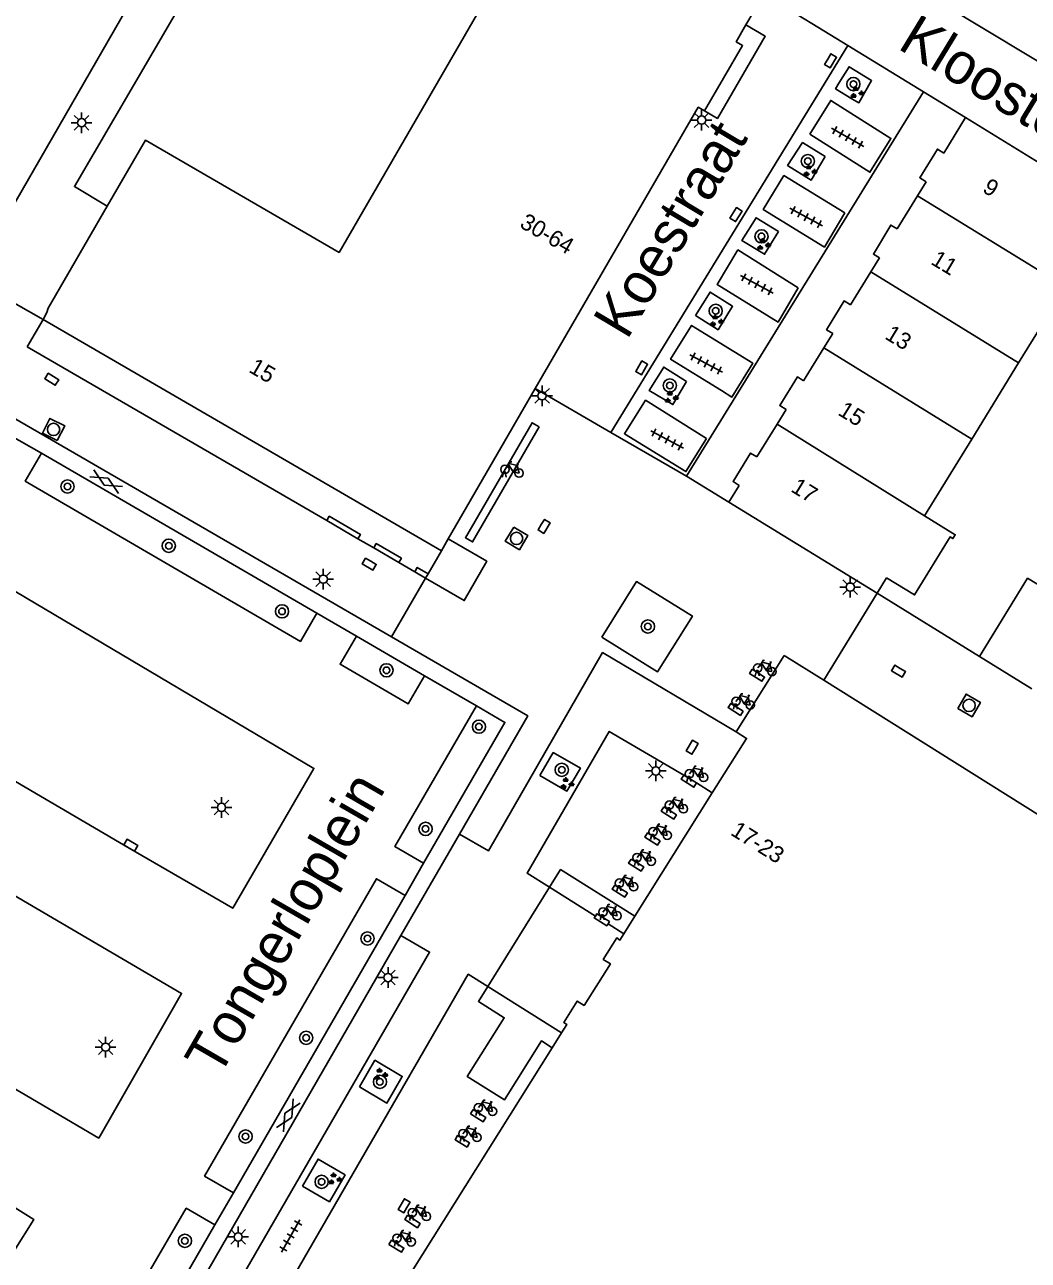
# Model space of a CAD drawing. Extents: x 136000 to 141014, y 402000 to 403500.
# Drawn here: x 138025.6 to 138086.4, y 402294.1 to 402368.9 of the extents above; entities that cross this region are included whole.
import ezdxf

# ---------------------------------------------------------------- set-up
doc = ezdxf.new("R2010")
doc.units = 0
for name, color, linetype in [('gg-afsc-hekwerk', 7, 'Continuous'), ('gg-afsc-muur', 7, 'Continuous'), ('gg-anno-huisnummerreeks BGT', 7, 'Continuous'), ('gg-anno-openbare ruimte label', 7, 'Continuous'), ('gg-bbg-bijgebouw', 7, 'Continuous'), ('gg-bbg-gedigitaliseerde bijgebouw', 7, 'Continuous'), ('gg-bbg-hoofdgebouw', 7, 'Continuous'), ('gg-bbg-luifel en loopbrug', 7, 'Continuous'), ('gg-bbg-onder overbouw', 7, 'Continuous'), ('gg-bbg-pand overbouw', 7, 'Continuous'), ('gg-bbg-pilaar onder overbouw', 7, 'Continuous'), ('gg-bbg-pilaar pand', 7, 'Continuous'), ('gg-bbg-tussenscheiding', 7, 'Continuous'), ('gg-knt-verharding', 7, 'Continuous'), ('gg-knt-verharding nz', 7, 'Continuous'), ('gt-grn-weggrens', 7, 'Continuous'), ('gt-symb-boom', 7, 'Continuous'), ('gt-symb-fietsenrek', 7, 'Continuous'), ('gt-symb-gesloten verharding', 7, 'Continuous'), ('gt-symb-groenvak', 7, 'Continuous'), ('gt-symb-kolk', 7, 'Continuous'), ('gt-symb-lichtmast', 7, 'Continuous'), ('gt-symb-rioolschacht', 7, 'Continuous'), ('gt-symb-tegel verharding', 7, 'Continuous')]:
    doc.layers.add(name, color=color, linetype=linetype)

# ---------------------------------------------------------------- blocks, each defined once
blk = doc.blocks.new('gt0-GRVAK')
at = {"layer": 'gt-symb-groenvak'}
for p, q in [((-0.11, 0.189), (-0.228, 0.24)), ((-0.182, 0.153), (0.088, 0.153)), ((-0.091, 0.211), (-0.156, 0.322)), ((-0.047, 0.214), (-0.047, 0.393)), ((-0.004, 0.211), (0.061, 0.322)), ((0.015, 0.189), (0.133, 0.24)), ((0.262, -0.052), (0.197, 0.059)), ((0.305, -0.049), (0.305, 0.13)), ((0.349, -0.052), (0.414, 0.059)), ((-0.245, -0.228), (-0.363, -0.177)), ((-0.318, -0.264), (-0.047, -0.264)), ((-0.226, -0.206), (-0.291, -0.095)), ((-0.183, -0.203), (-0.183, -0.024)), ((-0.139, -0.206), (-0.074, -0.095)), ((-0.12, -0.228), (-0.002, -0.177)), ((0.243, -0.074), (0.125, -0.023)), ((0.17, -0.11), (0.441, -0.11)), ((0.368, -0.074), (0.486, -0.023))]:
    blk.add_line(p, q, dxfattribs=at)
blk = doc.blocks.new('gt0-TEG1')
at = {"layer": 'gt-symb-tegel verharding'}
for p, q in [((-1.125, 0), (1.125, 0)), ((-0.9, -0.25), (-0.9, 0.25)), ((-0.45, -0.25), (-0.45, 0.25)), ((0, -0.25), (0, 0.25)), ((0.45, -0.25), (0.45, 0.25)), ((0.9, -0.25), (0.9, 0.25))]:
    blk.add_line(p, q, dxfattribs=at)
blk = doc.blocks.new('gt0-BOOM')
at = {"layer": 'gt-symb-boom'}
for radius in [0.4, 0.2]:
    blk.add_circle((0, 0), radius, dxfattribs=at)
blk = doc.blocks.new('gt0-KOLK')
at = {"layer": 'gt-symb-kolk'}
blk.add_lwpolyline([(0, 0), (0.375, 0), (0.375, 0.4), (-0.375, 0.4), (-0.375, 0), (0, 0)], dxfattribs=at)
blk = doc.blocks.new('gt0-LMAST')
at = {"layer": 'gt-symb-lichtmast'}
for p, q in [((-0.182, 0.173), (-0.447, 0.438)), ((-0.005, 0.246), (-0.005, 0.621)), ((0.172, 0.173), (0.437, 0.438)), ((-0.255, -0.004), (-0.63, -0.004)), ((-0.182, -0.181), (-0.447, -0.446)), ((-0.005, -0.254), (-0.005, -0.629)), ((0.437, -0.446), (0.172, -0.181)), ((0.245, -0.004), (0.62, -0.004))]:
    blk.add_line(p, q, dxfattribs=at)
blk.add_circle((-0.005, -0.004), 0.25, dxfattribs=at)
blk = doc.blocks.new('gt0-RS')
at = {"layer": 'gt-symb-rioolschacht'}
blk.add_lwpolyline([(-0.5, -0.5), (0.5, -0.5), (0.5, 0.5), (-0.5, 0.5)], close=True, dxfattribs=at)
blk.add_circle((0, 0), 0.375, dxfattribs=at)
blk = doc.blocks.new('gt0-FREK')
at = {"layer": 'gt-symb-fietsenrek'}
for p, q in [((0.259, 0.762), (0.294, 0.823)), ((0.54, 0.335), (0.259, 0.762)), ((0.294, 0.823), (0.767, 0.714)), ((0.757, 0.841), (0.866, 0.816)), ((0.767, 0.714), (0.84, 0.822)), ((0.767, 0.714), (0.54, 0.335)), ((0.895, 0.252), (0.767, 0.714))]:
    blk.add_line(p, q, dxfattribs=at)
for points in [[(0.036, 0.476), (0.228, 0.708), (0.259, 0.762)], [(0.294, 0.823), (0.36, 0.937), (0.452, 0.935)], [(-0.124, 0), (-0.047, 0.312), (0.053, 0.312), (0.12, 0)], [(0.54, 0.335), (0.555, 0.305), (0.895, 0.252)]]:
    blk.add_lwpolyline(points, dxfattribs=at)
for centre in [(0.036, 0.476), (0.895, 0.252)]:
    blk.add_circle(centre, 0.252, dxfattribs=at)
blk = doc.blocks.new('gt0-GESVH1')
at = {"layer": 'gt-symb-gesloten verharding'}
for p, q in [((-0.992, -0.261), (0.008, 0.239)), ((0.008, -0.261), (-0.992, 0.239)), ((0.008, 0.239), (1.008, -0.261)), ((1.008, 0.239), (0.008, -0.261))]:
    blk.add_line(p, q, dxfattribs=at)

msp = doc.modelspace()

# ---------------------------------------------------------------- linework, layer by layer
at = {"layer": 'gg-afsc-hekwerk'}
msp.add_lwpolyline([(138030.63, 402357.914), (138028.649, 402359.103), (138041.892, 402381.79)], dxfattribs=at)
at = {"layer": 'gg-afsc-muur'}
msp.add_line((138083.443, 402330.652), (138077.24, 402334.501), dxfattribs=at)
at = {"layer": 'gg-bbg-bijgebouw'}
msp.add_line((138086.593, 402328.703), (138083.443, 402330.652), dxfattribs=at)
at = {"layer": 'gg-bbg-gedigitaliseerde bijgebouw'}
msp.add_lwpolyline([(138087.459, 402334.706), (138086.344, 402335.391), (138083.443, 402330.652)], dxfattribs=at)
at = {"layer": 'gg-bbg-hoofdgebouw'}
for p, q in [((138033.741, 402373.25), (138022.397, 402353.534)), ((138069.3, 402368.888), (138070.387, 402370.763)), ((138081.273, 402361.135), (138082.596, 402363.284)), ((138082.596, 402363.284), (138091.544, 402357.769)), ((138079.684, 402358.553), (138080.207, 402359.402)), ((138078.445, 402356.541), (138079.684, 402358.553)), ((138027.063, 402351.754), (138030.63, 402357.914)), ((138076.849, 402353.947), (138077.374, 402354.801)), ((138075.621, 402351.952), (138076.849, 402353.947)), ((138088.636, 402353.038), (138085.803, 402348.43)), ((138074.013, 402349.338), (138074.549, 402350.209)), ((138072.788, 402347.348), (138074.013, 402349.338)), ((138085.803, 402348.43), (138082.969, 402343.82)), ((138051.276, 402337.772), (138056.547, 402346.876)), ((138071.178, 402344.731), (138071.723, 402345.616)), ((138069.954, 402342.742), (138071.178, 402344.731)), ((138082.969, 402343.82), (138080.11, 402339.17)), ((138068.264, 402339.997), (138068.89, 402341.014)), ((138077.24, 402334.501), (138068.264, 402339.997)), ((138050.86, 402337.054), (138051.276, 402337.772)), ((138077.807, 402335.423), (138077.24, 402334.501)), ((138068.709, 402326.089), (138071.619, 402330.716)), ((138074.005, 402329.218), (138071.619, 402330.716)), ((138107.245, 402308.347), (138074.005, 402329.218)), ((138067.262, 402322.4), (138062.573, 402314.932)), ((138062.573, 402314.932), (138061.905, 402313.868)), ((138058.143, 402307.877), (138057.574, 402306.97)), ((138057.574, 402306.97), (138048.127, 402291.924))]:
    msp.add_line(p, q, dxfattribs=at)
for points in [[(138045.53, 402379.667), (138043.434, 402376.045), (138053.436, 402370.256), (138044.669, 402355.118), (138032.944, 402361.909), (138030.63, 402357.914)], [(138066.797, 402363.682), (138069.098, 402367.642), (138068.709, 402367.868), (138069.3, 402368.888)], [(138056.547, 402346.876), (138066.408, 402363.908), (138066.797, 402363.682)], [(138081.273, 402361.135), (138080.886, 402361.373), (138079.82, 402359.64), (138080.207, 402359.402)], [(138078.445, 402356.541), (138078.063, 402356.776), (138077.013, 402355.023), (138077.374, 402354.801)], [(138027.063, 402351.754), (138026.987, 402351.476), (138026.75, 402351.068)], [(138075.621, 402351.952), (138075.239, 402352.187), (138074.175, 402350.439), (138074.549, 402350.209)], [(138072.788, 402347.348), (138072.412, 402347.579), (138071.345, 402345.849), (138071.723, 402345.616)], [(138069.954, 402342.742), (138069.579, 402342.973), (138068.516, 402341.244), (138068.89, 402341.014)], [(138080.11, 402339.17), (138081.97, 402338.031), (138081.824, 402337.792), (138081.653, 402337.896), (138079.502, 402334.384), (138077.807, 402335.423)], [(138068.709, 402326.089), (138069.336, 402325.703), (138067.262, 402322.4)], [(138058.143, 402307.877), (138058.46, 402308.38), (138058.281, 402308.492), (138059.083, 402309.799), (138059.504, 402309.534), (138061.092, 402312.05), (138060.665, 402312.32), (138061.476, 402313.618), (138061.671, 402313.495), (138061.905, 402313.868)]]:
    msp.add_lwpolyline(points, dxfattribs=at)
at = {"layer": 'gg-bbg-luifel en loopbrug'}
for p, q in [((138050.057, 402335.668), (138049.907, 402335.409)), ((138057.412, 402316.689), (138053.668, 402310.687))]:
    msp.add_line(p, q, dxfattribs=at)
for points in [[(138049.907, 402335.409), (138052.249, 402334.048), (138053.608, 402336.422), (138051.276, 402337.772)], [(138062.573, 402314.932), (138058.077, 402317.755), (138057.412, 402316.689)], [(138053.668, 402310.687), (138053.101, 402309.778), (138054.671, 402308.793), (138052.429, 402305.234), (138054.68, 402303.816), (138056.918, 402307.382), (138057.574, 402306.97)]]:
    msp.add_lwpolyline(points, dxfattribs=at)
at = {"layer": 'gg-bbg-onder overbouw'}
msp.add_line((138026.75, 402351.068), (138050.86, 402337.054), dxfattribs=at)
at = {"layer": 'gg-bbg-pand overbouw'}
for p, q in [((138026.75, 402351.068), (138025.785, 402349.406)), ((138043.924, 402338.887), (138025.785, 402349.406)), ((138045.809, 402337.791), (138046.769, 402337.233)), ((138050.86, 402337.054), (138050.057, 402335.668)), ((138048.29, 402336.349), (138049.25, 402335.791))]:
    msp.add_line(p, q, dxfattribs=at)
at = {"layer": 'gg-bbg-pilaar onder overbouw'}
for points in [[(138045.809, 402337.791), (138045.959, 402338.048), (138044.075, 402339.146), (138043.924, 402338.887)], [(138048.29, 402336.349), (138048.44, 402336.606), (138046.92, 402337.492), (138046.769, 402337.233)], [(138049.25, 402335.791), (138049.401, 402336.05), (138050.057, 402335.668)]]:
    msp.add_lwpolyline(points, dxfattribs=at)
at = {"layer": 'gg-bbg-pilaar pand'}
for p, q in [((138045.809, 402337.791), (138043.924, 402338.887)), ((138048.29, 402336.349), (138046.769, 402337.233)), ((138049.25, 402335.791), (138049.907, 402335.409))]:
    msp.add_line(p, q, dxfattribs=at)
at = {"layer": 'gg-bbg-tussenscheiding'}
for p, q in [((138088.636, 402353.038), (138079.684, 402358.553)), ((138085.803, 402348.43), (138076.849, 402353.947)), ((138082.969, 402343.82), (138074.013, 402349.338)), ((138071.178, 402344.731), (138080.11, 402339.17))]:
    msp.add_line(p, q, dxfattribs=at)
at = {"layer": 'gg-knt-verharding'}
for p, q in [((138080.038, 402364.851), (138065.707, 402341.567)), ((138082.596, 402363.284), (138080.038, 402364.851)), ((137995.797, 402362.023), (138047.834, 402331.843)), ((138024.709, 402344.086), (138026.652, 402342.958)), ((138026.652, 402342.958), (138043.324, 402333.279)), ((138065.707, 402341.567), (138068.264, 402339.997)), ((138043.324, 402333.279), (138045.721, 402331.888)), ((138045.721, 402331.888), (138049.842, 402329.495)), ((138049.842, 402329.495), (138052.98, 402327.674)), ((138051.963, 402319.908), (138048.417, 402313.759)), ((138049.79, 402318.144), (138048.666, 402316.196)), ((138038.275, 402298.199), (138048.666, 402316.196)), ((138048.417, 402313.759), (138032.769, 402286.624)), ((138038.275, 402298.199), (138037.152, 402296.255)), ((138037.152, 402296.255), (138032.303, 402287.855))]:
    msp.add_line(p, q, dxfattribs=at)
for points in [[(138081.262, 402370.123), (138109.96, 402352.86), (138110.309, 402353.333)], [(138074.929, 402365.366), (138075.54, 402366.359), (138076.901, 402365.519), (138076.135, 402364.179), (138075.701, 402364.427), (138074.722, 402365.029), (138074.929, 402365.366)], [(138073.164, 402362.276), (138074.427, 402364.326), (138078.068, 402362.023), (138076.804, 402359.973), (138073.164, 402362.276)], [(138074.092, 402360.934), (138072.729, 402361.772), (138071.819, 402360.385), (138073.235, 402359.491), (138074.092, 402360.934)], [(138075.284, 402357.526), (138071.599, 402359.773), (138070.347, 402357.72), (138074.042, 402355.441), (138075.284, 402357.526)], [(138071.262, 402356.392), (138069.912, 402357.214), (138069.048, 402355.847), (138070.43, 402355.007), (138071.262, 402356.392)], [(138072.456, 402352.985), (138068.811, 402355.272), (138067.552, 402353.184), (138071.246, 402350.907), (138072.456, 402352.985)], [(138066.249, 402351.296), (138067.122, 402352.72), (138068.485, 402351.859), (138067.612, 402350.435), (138066.249, 402351.296)], [(138067.815, 402346.752), (138068.45, 402346.36), (138069.711, 402348.406), (138066.009, 402350.701), (138064.737, 402348.649), (138067.815, 402346.752)], [(138065.698, 402347.299), (138064.326, 402348.179), (138063.447, 402346.758), (138064.873, 402345.907), (138065.698, 402347.299)], [(138066.917, 402343.861), (138063.22, 402346.174), (138061.945, 402344.144), (138065.666, 402341.849), (138066.917, 402343.861)], [(138043.324, 402333.279), (138042.333, 402331.574), (138025.675, 402341.275), (138026.652, 402342.958)], [(138060.577, 402331.828), (138062.668, 402335.191), (138066.058, 402333.104), (138063.941, 402329.729), (138060.577, 402331.828)], [(138049.842, 402329.495), (138048.854, 402327.793), (138044.736, 402330.192), (138045.721, 402331.888)], [(138047.834, 402331.843), (138056.086, 402327.057), (138051.963, 402319.908)], [(138052.98, 402327.674), (138048.051, 402319.148), (138049.79, 402318.144)], [(138052.98, 402327.674), (138054.712, 402326.668), (138049.79, 402318.144)], [(138056.815, 402323.448), (138057.63, 402324.842), (138059.28, 402323.901), (138058.466, 402322.508), (138056.815, 402323.448)], [(138048.666, 402316.196), (138046.928, 402317.2), (138036.53, 402299.207), (138038.275, 402298.199)], [(138045.905, 402304.599), (138046.841, 402306.217), (138048.499, 402305.239), (138047.563, 402303.622), (138045.905, 402304.599)], [(138042.449, 402298.6), (138044.083, 402297.646), (138045.03, 402299.278), (138043.396, 402300.232), (138042.449, 402298.6)], [(138037.152, 402296.255), (138035.423, 402297.253), (138030.542, 402288.872)]]:
    msp.add_lwpolyline(points, dxfattribs=at)
at = {"layer": 'gg-knt-verharding nz'}
for p, q in [((138065.543, 402323.48), (138066.305, 402323.001)), ((138066.305, 402323.001), (138067.262, 402322.4)), ((138057.412, 402316.689), (138060.185, 402314.948)), ((138060.948, 402314.469), (138061.905, 402313.868)), ((138053.668, 402310.687), (138058.143, 402307.877))]:
    msp.add_line(p, q, dxfattribs=at)
for points in [[(138066.797, 402363.682), (138067.575, 402363.23), (138070.469, 402368.21), (138069.3, 402368.888)], [(138003.552, 402347.348), (138043.148, 402323.882), (138038.232, 402315.418), (138031.959, 402319.064), (137998.48, 402338.693), (138003.552, 402347.348)], [(138056.787, 402344.562), (138052.748, 402337.599), (138052.315, 402337.849), (138056.354, 402344.813), (138056.787, 402344.562)], [(137995.392, 402333.558), (137990.32, 402324.831), (138015.654, 402310.002), (138030.126, 402301.509), (138035.137, 402310.26), (137995.392, 402333.558)], [(138068.709, 402326.089), (138060.624, 402330.896), (138053.718, 402318.896), (138051.963, 402319.908)], [(138069.677, 402329.886), (138070.421, 402329.417), (138070.262, 402329.163), (138069.517, 402329.632), (138069.677, 402329.886)], [(138069.12, 402327.347), (138068.375, 402327.816), (138068.215, 402327.562), (138068.96, 402327.093), (138069.12, 402327.347)], [(138065.543, 402323.48), (138061.021, 402326.124), (138056.061, 402317.538), (138057.412, 402316.689)], [(138066.305, 402323.001), (138066.146, 402322.747), (138065.383, 402323.226), (138065.543, 402323.48)], [(138064.33, 402321.549), (138065.093, 402321.07), (138064.933, 402320.816), (138064.171, 402321.295), (138064.33, 402321.549)], [(138025.011, 402294.673), (138026.198, 402296.567), (137987.886, 402320.531), (137986.716, 402318.662), (137986.789, 402318.617)], [(138064.103, 402319.495), (138063.341, 402319.974), (138063.182, 402319.72), (138063.944, 402319.241), (138064.103, 402319.495)], [(138062.352, 402318.398), (138063.114, 402317.92), (138062.955, 402317.666), (138062.193, 402318.144), (138062.352, 402318.398)], [(138062.125, 402316.345), (138061.363, 402316.823), (138061.204, 402316.569), (138061.966, 402316.091), (138062.125, 402316.345)], [(138060.948, 402314.469), (138060.876, 402314.354), (138060.113, 402314.833), (138060.185, 402314.948)], [(138060.948, 402314.469), (138061.035, 402314.608), (138060.273, 402315.087), (138060.185, 402314.948)], [(138034.439, 402285.58), (138050.144, 402312.763), (138048.417, 402313.759)], [(138040.389, 402290.503), (138052.491, 402311.426), (138053.668, 402310.687)], [(138052.634, 402302.971), (138053.401, 402302.494), (138053.559, 402302.749), (138052.792, 402303.226), (138052.634, 402302.971)], [(138052.414, 402300.956), (138051.688, 402301.407), (138051.847, 402301.662), (138052.572, 402301.211), (138052.414, 402300.956)], [(138048.806, 402296.829), (138049.579, 402296.324), (138049.415, 402296.073), (138048.642, 402296.578), (138048.806, 402296.829)], [(138047.683, 402295.062), (138048.44, 402294.593), (138048.598, 402294.847), (138047.841, 402295.317), (138047.683, 402295.062)]]:
    msp.add_lwpolyline(points, dxfattribs=at)
at = {"layer": 'gt-grn-weggrens'}
for p, q in [((138075.474, 402367.647), (138070.387, 402370.763)), ((138075.474, 402367.647), (138061.125, 402344.223)), ((138080.038, 402364.851), (138075.474, 402367.647)), ((138026.75, 402351.068), (138022.397, 402353.534)), ((138061.125, 402344.223), (138056.547, 402346.876)), ((138065.707, 402341.567), (138061.125, 402344.223)), ((138049.907, 402335.409), (138047.834, 402331.843)), ((138074.005, 402329.218), (138077.24, 402334.501))]:
    msp.add_line(p, q, dxfattribs=at)

# ---------------------------------------------------------------- block references
at = {"layer": 'gt-symb-boom'}
for p, rotation in [((138075.8, 402365.311), -128.66875373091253), ((138073.047, 402360.648), -152.79408316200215), ((138070.243, 402356.091), -152.79408316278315), ((138067.465, 402351.578), -152.79408316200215), ((138064.687, 402347.064), -152.79408316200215), ((138058.147, 402323.797), 58.12218352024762)]:
    msp.add_blockref('gt0-BOOM', p, dxfattribs=dict(at, rotation=rotation))
for p in [(138028.229, 402340.951), (138034.361, 402337.363), (138041.217, 402333.392), (138063.364, 402332.47), (138047.544, 402329.821), (138053.137, 402326.409), (138049.907, 402320.22), (138046.388, 402313.588), (138042.675, 402307.571), (138047.144, 402304.906), (138039.012, 402301.601), (138043.615, 402298.853), (138035.341, 402295.281)]:
    msp.add_blockref('gt0-BOOM', p, dxfattribs=at)
at = {"layer": 'gt-symb-fietsenrek'}
for p in [(138054.674, 402341.509), (138069.978, 402329.489), (138068.659, 402327.467), (138065.84, 402323.082), (138064.622, 402321.186), (138063.64, 402319.58), (138062.671, 402318.01), (138061.606, 402316.467), (138060.602, 402314.709), (138053.067, 402302.87), (138052.126, 402301.293), (138049.061, 402296.512), (138048.141, 402294.969)]:
    msp.add_blockref('gt0-FREK', p, dxfattribs=at)
at = {"layer": 'gt-symb-gesloten verharding'}
for p, rotation in [((138030.574, 402341.233), 149.66519417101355), ((138041.587, 402302.881), 59.949676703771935)]:
    msp.add_blockref('gt0-GESVH1', p, dxfattribs=dict(at, rotation=rotation))
at = {"layer": 'gt-symb-groenvak'}
for p in [(138075.994, 402364.786), (138073.139, 402360.046), (138070.34, 402355.592), (138067.485, 402350.966), (138064.744, 402346.341), (138058.434, 402322.959), (138047.16, 402305.355), (138044.385, 402299.024)]:
    msp.add_blockref('gt0-GRVAK', p, dxfattribs=at)
at = {"layer": 'gt-symb-kolk'}
for p, rotation in [((138074.25, 402366.823), -120.92445901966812), ((138068.522, 402357.516), -121.59249156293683), ((138062.811, 402348.23), -120.12860024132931), ((138027.384, 402347.613), 148.4075084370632), ((138056.909, 402338.639), -121.41597875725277), ((138046.596, 402336.422), 149.79306598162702), ((138078.637, 402329.94), 148.07354491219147), ((138066.218, 402325.064), 59.949676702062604), ((138031.959, 402319.064), -30.1762780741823), ((138048.781, 402297.309), 59.94967670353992)]:
    msp.add_blockref('gt0-KOLK', p, dxfattribs=dict(at, rotation=rotation))
at = {"layer": 'gt-symb-lichtmast'}
for p in [(138029.093, 402362.975), (138066.62, 402363.133), (138056.962, 402346.442), (138043.717, 402335.344), (138075.615, 402334.861), (138063.848, 402323.734), (138037.56, 402321.526), (138047.637, 402311.227), (138030.547, 402307.011), (138038.568, 402295.524)]:
    msp.add_blockref('gt0-LMAST', p, dxfattribs=at)
at = {"layer": 'gt-symb-rioolschacht'}
for p, rotation in [((138027.39, 402344.403), 63.204435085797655), ((138055.412, 402337.805), -120.8752916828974), ((138082.802, 402327.698), -30.128600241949)]:
    msp.add_blockref('gt0-RS', p, dxfattribs=dict(at, rotation=rotation))
at = {"layer": 'gt-symb-tegel verharding'}
for p, rotation in [((138075.455, 402362.084), -29.410819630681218), ((138072.945, 402357.26), -28.10282356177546), ((138069.961, 402353.188), -28.10282356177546), ((138066.894, 402348.392), -28.102823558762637), ((138064.524, 402343.791), -28.102823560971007), ((138041.743, 402295.583), 60.07751301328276)]:
    msp.add_blockref('gt0-TEG1', p, dxfattribs=dict(at, rotation=rotation))

# ---------------------------------------------------------------- texts
at = {"layer": 'gg-anno-huisnummerreeks BGT'}
for s, rotation, p in [('9', 328.4, (138083.555, 402358.819)), ('30-64', 329.9, (138055.542, 402356.681)), ('11', 329.1, (138080.425, 402354.448)), ('13', 328.7, (138077.64, 402349.933)), ('15', 329.8, (138039.144, 402347.913)), ('15', 328.3, (138074.806, 402345.322)), ('17', 328.4, (138071.955, 402340.684)), ('17-23', 327.9, (138068.305, 402319.898))]:
    msp.add_text(s, height=1, rotation=rotation, dxfattribs=at).set_placement(p)
at = {"layer": 'gg-anno-openbare ruimte label'}
for s, rotation, p in [('Kloosterpad', 328.7, (138078.411, 402367.498)), ('Koestraat', 59.1, (138062.098, 402349.775)), ('Tongerloplein', 60, (138037.394, 402305.117))]:
    msp.add_text(s, height=2.5, rotation=rotation, dxfattribs=at).set_placement(p)

doc.saveas('drawing.dxf')
